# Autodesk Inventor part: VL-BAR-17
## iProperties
Created: 2005-08
Part Number: VL-BAR-17
Document SubType Name: Sheet Metal
Density: 1 g/cm^3
Mass: 2.87425 g
Surface Area: 55.6033 cm^2
Volume: 2.87425 cm^3
Sheet Metal Rule: Default
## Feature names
1. Rectangular Pattern1
2. Plate1
